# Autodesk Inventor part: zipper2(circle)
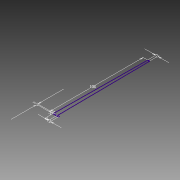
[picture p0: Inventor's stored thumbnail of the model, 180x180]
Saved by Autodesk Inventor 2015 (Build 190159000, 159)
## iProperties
Created: 2015-02
Part Number: zipper2(circle)
Material: Generic
Document SubType Name: Modeling
Designer: sungeun
Density: 1 g/cm^3
Appearance: Default
Author: sungeun
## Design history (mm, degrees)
sketch "Sketch1"
  geometry: L1 (0, 0)-(0, 1); L2 (0, 1)-(1, 100); L3 (1, 100)-(3, 100); L4 (3, 100)-(4, 1); L5 (4, 1)-(6, 1); L6 (6, 1)-(6, 0); L7 (6, 0)-(0, 0); L8 (0, 1)-(4, 1); 2 further points
  constraints: 16 end point, 2 midpoint, 2 perpendicular, 2 vertical, 1 parallel, 1 vertical alignment
  dimensions: "d0" = 1 distance of L1.start L1.end; "d1" = 100 distance between parallel lines of L7 L3; "d2" = 1 distance between parallel lines of L7 L5; "d3" = 2 distance of L2.end L3.end; "d4" = 4 distance of L4.end L1.end; "d5" = 2 distance of L4.end L5.end
